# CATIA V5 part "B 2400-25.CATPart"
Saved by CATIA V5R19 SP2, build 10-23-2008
Part number: B 2400-25
Bounding box of the stored display mesh (mm): x -37.351 to 37.351, y -37.351 to 37.351, z 0 to 160
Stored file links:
  C:\Users\Bora\Desktop\3D Katı model\B serisi\B 2400\B 2400-25.CATPart
  C:\Program Files\Dassault Systemes\B19\intel_a\reffiles\standard\MetricThickPitch.txt
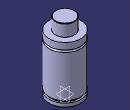
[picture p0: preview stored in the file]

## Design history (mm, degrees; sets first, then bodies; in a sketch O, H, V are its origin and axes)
Body1 (main body)
  Sketch1 on yz-plane, origin (0, 0, 0), H (0, 1, 0), V (0, 0, 1)
    point P3 (22.5, 159)
    point P5 (22.5, 159)
    point P10 (37.5, 111.5)
    point P11 (37.5, 116.5)
    point P13 (37.5, 116.5)
    point P14 (37.5, 111.5)
    line L1 (37.5, 0) -> (37.5, 8)
    line L2 (22.5, 159) -> (22.5, 132)
    arc A1 centre (21.5, 159) radius 1 from (22.5, 159) to (21.5, 160) ccw
    line L3 (33.5, 13) -> (33.5, 8)
    line L4 (37.5, 13) -> (37.5, 111.5)
    line L5 (37.5, 116.5) -> (37.5, 132)
    arc A2 centre (37.5, 114) radius 2.5 from (37.5, 116.5) to (37.5, 111.5) ccw
    line L6 (21.5, 160) -> (0, 160)
    point P15 (0, 160)
    line L7 (22.5, 132) -> (37.5, 132)
    line L8 (0, 0) -> (37.5, 0)
    line L9 (33.5, 13) -> (37.5, 13)
    line L10 (33.5, 8) -> (37.5, 8)
    coincidence: P15 V, P3 P5, P10 P14, P11 P13
    tangency: L6 A1
    horizontal: L7 H, L8 H, L9 H, L10 H
  Shaft1: profile Sketch1, axis Sketch1.V, angle 360
  Sketch2 on face of Shaft1 from Sketch1.L8, origin (0, 0, 0), H (1, 0, 0), V (0, -1, 0)
    point P1 (20, 0)
    distance P1 V = 20
  Hole1: placed by Sketch2, at (20, 0, 0) direction (0, 0, 1), diameter 6.647, depth 13, threaded "M8", thread diameter 8, thread depth 13, pitch 1.25
  CircPattern1: of Hole1, instances 4, angular step 90, axis from xy-plane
